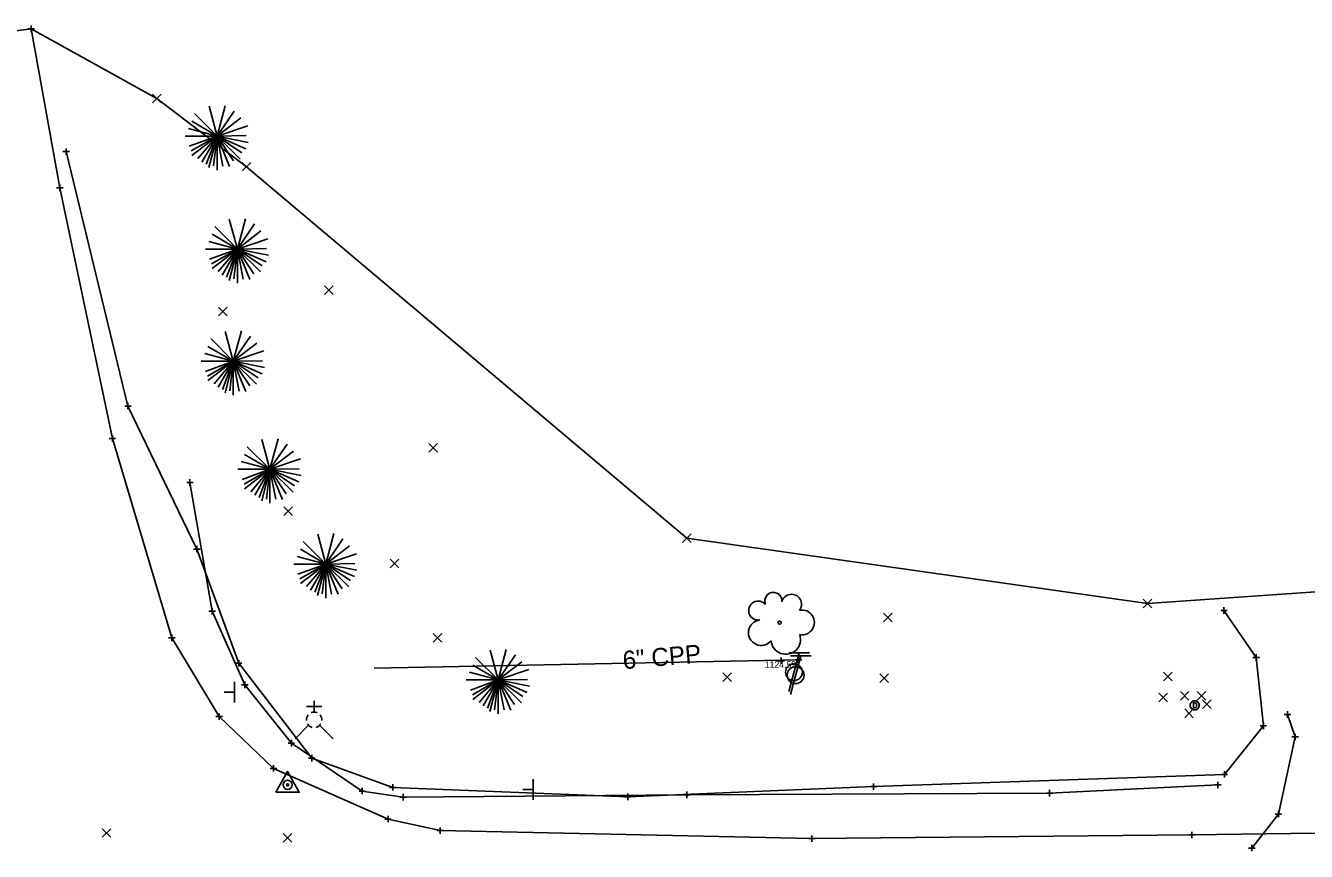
# Model space of a CAD drawing. Extents: x 146022 to 147632, y 437624 to 440659.
# Drawn here: x 147167.5 to 147365.2, y 438638.5 to 438766 of the extents above; entities that cross this region are included whole.
import ezdxf

# ---------------------------------------------------------------- set-up
doc = ezdxf.new("R2010")
doc.units = 0
for name, color, linetype in [('_CIVIL_CONSTRUCTION', 7, 'Continuous'), ('DR_P_Paved_Gutter', 7, 'Continuous'), ('DR_X_Storm_Sewer', 7, 'Continuous'), ('DR_X_Text', 7, 'Continuous'), ('DT_X_Break_Line', 7, 'Continuous'), ('DT_X_Triangles', 7, 'Continuous'), ('DT_X_Void', 7, 'Continuous'), ('PF_X_Ground_Line', 7, 'Continuous'), ('PV_P_Joint', 7, 'Continuous'), ('RD_P_Anchor_Assembly', 7, 'Continuous'), ('RD_P_GR_Lt_Replaced', 7, 'Continuous'), ('RD_P_GR_Rt', 7, 'Continuous'), ('SC_Scratch1', 7, 'Continuous'), ('SN_X_Post', 7, 'Continuous'), ('SV_X_Terrain_Boundary', 7, 'Continuous'), ('UT_X_Electric', 7, 'Continuous'), ('UT_X_Overhead_Cable_TV', 7, 'Continuous'), ('UT_X_Overhead_Electric', 7, 'Continuous')]:
    doc.layers.add(name, color=color, linetype=linetype)

msp = doc.modelspace()

# ---------------------------------------------------------------- linework, layer by layer
at = {"layer": '_CIVIL_CONSTRUCTION'}
for p, q in [((147187.08, 438754.06), (147188.42, 438755.39)), ((147187.08, 438755.39), (147188.42, 438754.06)), ((147200.92, 438743.53), (147202.25, 438744.86)), ((147200.92, 438744.86), (147202.25, 438743.53)), ((147213.61, 438724.44), (147214.94, 438725.78)), ((147213.61, 438725.78), (147214.94, 438724.44)), ((147197.27, 438721.15), (147198.61, 438722.49)), ((147197.27, 438722.49), (147198.61, 438721.15)), ((147229.75, 438700.13), (147231.09, 438701.47)), ((147229.75, 438701.47), (147231.09, 438700.13)), ((147207.34, 438690.37), (147208.68, 438691.7)), ((147207.34, 438691.7), (147208.68, 438690.37)), ((147268.91, 438686.18), (147270.24, 438687.51)), ((147268.91, 438687.51), (147270.24, 438686.18)), ((147223.75, 438682.28), (147225.09, 438683.61)), ((147223.75, 438683.61), (147225.09, 438682.28)), ((147340.04, 438676.1), (147341.37, 438677.43)), ((147340.04, 438677.43), (147341.37, 438676.1)), ((147299.92, 438673.96), (147301.25, 438675.29)), ((147299.92, 438675.29), (147301.25, 438673.96)), ((147230.4, 438670.78), (147231.73, 438672.11)), ((147230.4, 438672.11), (147231.73, 438670.78)), ((147275.12, 438664.72), (147276.45, 438666.05)), ((147275.12, 438666.05), (147276.45, 438664.72)), ((147299.39, 438664.59), (147300.72, 438665.93)), ((147299.39, 438665.93), (147300.72, 438664.59)), ((147343.19, 438664.81), (147344.53, 438666.14)), ((147343.19, 438666.14), (147344.53, 438664.81)), ((147345.77, 438661.83), (147347.1, 438663.16)), ((147345.77, 438663.16), (147347.1, 438661.83)), ((147348.39, 438661.86), (147349.72, 438663.2)), ((147348.39, 438663.2), (147349.72, 438661.86)), ((147342.47, 438661.6), (147343.8, 438662.94)), ((147342.47, 438662.94), (147343.8, 438661.6)), ((147349.2, 438660.55), (147350.53, 438661.88)), ((147349.2, 438661.88), (147350.53, 438660.55)), ((147346.44, 438659.14), (147347.77, 438660.48)), ((147346.44, 438660.48), (147347.77, 438659.14)), ((147179.31, 438640.67), (147180.64, 438642)), ((147179.31, 438642), (147180.64, 438640.67)), ((147207.23, 438639.94), (147208.56, 438641.27)), ((147207.23, 438641.27), (147208.56, 438639.94))]:
    msp.add_line(p, q, dxfattribs=at)
at = {"layer": 'DR_P_Paved_Gutter'}
msp.add_lwpolyline([(147351.58, 438648.75), (147325.59, 438647.48), (147269.59, 438647.22), (147225.76, 438646.86), (147219.46, 438647.81), (147208.51, 438655.2), (147201.32, 438664.21), (147196.28, 438675.56), (147192.84, 438695.44)], dxfattribs=at)
at = {"layer": 'DR_X_Storm_Sewer'}
msp.add_line((147286.81, 438668.08), (147221.27, 438666.79), dxfattribs=at)
at = {"layer": 'DT_X_Break_Line'}
for p, q in [((147199.73, 438664.67), (147199.73, 438661.47)), ((147199.73, 438663.07), (147198.13, 438663.07))]:
    msp.add_line(p, q, dxfattribs=at)
at = {"layer": 'DT_X_Triangles'}
msp.add_line((147347.98, 438661.05), (147347.98, 438661.05), dxfattribs=at)
msp.add_line((147347.98, 438661.05), (147347.98, 438661.05), dxfattribs=at)
msp.add_line((147347.98, 438661.05), (147347.98, 438661.05), dxfattribs=at)
msp.add_line((147347.98, 438661.05), (147347.98, 438661.05), dxfattribs=at)
msp.add_line((147347.98, 438661.05), (147347.98, 438661.05), dxfattribs=at)
msp.add_circle((147347.98, 438661.05), 0.7, dxfattribs=at)
at = {"layer": 'DT_X_Void'}
for p, q in [((147197.02, 438748.91), (147193.53, 438752.39)), ((147197.02, 438748.91), (147195.79, 438753.52)), ((147197.02, 438748.91), (147198.28, 438753.6)), ((147197.02, 438748.91), (147199.68, 438752.79)), ((147197.02, 438748.91), (147193.11, 438751.2)), ((147197.02, 438748.91), (147200.68, 438751.71)), ((147197.02, 438748.91), (147201.76, 438750.51)), ((147192.09, 438748.91), (147197.02, 438748.91)), ((147197.02, 438748.91), (147192.61, 438750.09)), ((147197.02, 438748.91), (147192.73, 438747.34)), ((147197.02, 438748.91), (147193.04, 438746.62)), ((147197.02, 438748.91), (147193.11, 438745.91)), ((147197.02, 438748.91), (147194.08, 438745.44)), ((147197.02, 438748.91), (147194.7, 438744.89)), ((147197.02, 438748.91), (147195.36, 438744.57)), ((147197.02, 438748.91), (147195.76, 438744.05)), ((147197.02, 438748.91), (147196.48, 438744.31)), ((147197.02, 438748.91), (147201.53, 438749)), ((147197.02, 438743.67), (147197.02, 438748.91)), ((147197.02, 438748.91), (147197.94, 438744.27)), ((147197.02, 438748.91), (147198.95, 438744.24)), ((147197.02, 438748.91), (147199.56, 438745.11)), ((147197.02, 438748.91), (147200.61, 438745.38)), ((147197.02, 438748.91), (147200.84, 438746.35)), ((147197.02, 438748.91), (147201.49, 438746.96)), ((147197.02, 438748.91), (147201.85, 438747.95)), ((147200.16, 438731.47), (147196.67, 438734.95)), ((147200.16, 438731.47), (147198.92, 438736.08)), ((147200.16, 438731.47), (147201.41, 438736.17)), ((147200.16, 438731.47), (147202.81, 438735.35)), ((147200.16, 438731.47), (147195.74, 438732.65)), ((147200.16, 438731.47), (147196.25, 438733.76)), ((147200.16, 438731.47), (147203.81, 438734.27)), ((147200.16, 438731.47), (147204.89, 438733.07)), ((147195.22, 438731.47), (147200.16, 438731.47)), ((147200.16, 438731.47), (147195.87, 438729.91)), ((147200.16, 438731.47), (147196.17, 438729.19)), ((147200.16, 438731.47), (147196.25, 438728.47)), ((147200.16, 438731.47), (147197.21, 438728)), ((147200.16, 438731.47), (147197.84, 438727.45)), ((147200.16, 438731.47), (147198.49, 438727.13)), ((147200.16, 438731.47), (147198.89, 438726.61)), ((147200.16, 438731.47), (147199.61, 438726.88)), ((147200.16, 438731.47), (147204.67, 438731.56)), ((147200.16, 438726.23), (147200.16, 438731.47)), ((147200.16, 438731.47), (147201.08, 438726.83)), ((147200.16, 438731.47), (147202.09, 438726.8)), ((147200.16, 438731.47), (147202.69, 438727.67)), ((147200.16, 438731.47), (147203.74, 438727.95)), ((147200.16, 438731.47), (147203.98, 438728.91)), ((147200.16, 438731.47), (147204.62, 438729.53)), ((147200.16, 438731.47), (147204.98, 438730.51)), ((147199.54, 438714.16), (147198.3, 438718.77)), ((147199.54, 438714.16), (147200.79, 438718.86)), ((147199.54, 438714.16), (147196.05, 438717.65)), ((147199.54, 438714.16), (147202.19, 438718.05)), ((147199.54, 438714.16), (147203.19, 438716.97)), ((147199.54, 438714.16), (147195.12, 438715.34)), ((147199.54, 438714.16), (147195.63, 438716.46)), ((147199.54, 438714.16), (147204.27, 438715.77)), ((147194.6, 438714.16), (147199.54, 438714.16)), ((147199.54, 438714.16), (147195.25, 438712.6)), ((147199.54, 438714.16), (147195.55, 438711.88)), ((147199.54, 438714.16), (147195.63, 438711.17)), ((147199.54, 438714.16), (147196.59, 438710.69)), ((147199.54, 438714.16), (147197.22, 438710.15)), ((147199.54, 438714.16), (147197.87, 438709.82)), ((147199.54, 438714.16), (147198.27, 438709.3)), ((147199.54, 438714.16), (147199, 438709.57)), ((147199.54, 438714.16), (147204.05, 438714.25)), ((147199.54, 438708.92), (147199.54, 438714.16)), ((147199.54, 438714.16), (147200.46, 438709.52)), ((147199.54, 438714.16), (147201.47, 438709.49)), ((147199.54, 438714.16), (147202.07, 438710.37)), ((147199.54, 438714.16), (147203.13, 438710.64)), ((147199.54, 438714.16), (147203.36, 438711.61)), ((147199.54, 438714.16), (147204, 438712.22)), ((147199.54, 438714.16), (147204.37, 438713.2)), ((147205.18, 438697.48), (147201.69, 438700.97)), ((147205.18, 438697.48), (147203.95, 438702.1)), ((147205.18, 438697.48), (147206.44, 438702.18)), ((147205.18, 438697.48), (147207.84, 438701.37)), ((147205.18, 438697.48), (147201.28, 438699.78)), ((147205.18, 438697.48), (147208.84, 438700.29)), ((147205.18, 438697.48), (147209.92, 438699.09)), ((147200.25, 438697.48), (147205.18, 438697.48)), ((147205.18, 438697.48), (147200.77, 438698.67)), ((147205.18, 438697.48), (147200.89, 438695.92)), ((147205.18, 438697.48), (147201.2, 438695.2)), ((147205.18, 438697.48), (147201.28, 438694.49)), ((147205.18, 438697.48), (147202.24, 438694.02)), ((147205.18, 438697.48), (147202.87, 438693.47)), ((147205.18, 438697.48), (147203.52, 438693.14)), ((147205.18, 438697.48), (147203.92, 438692.63)), ((147205.18, 438697.48), (147204.64, 438692.89)), ((147205.18, 438697.48), (147209.69, 438697.57)), ((147205.18, 438692.24), (147205.18, 438697.48)), ((147205.18, 438697.48), (147206.11, 438692.85)), ((147205.18, 438697.48), (147207.12, 438692.81)), ((147205.18, 438697.48), (147207.72, 438693.69)), ((147205.18, 438697.48), (147208.77, 438693.96)), ((147205.18, 438697.48), (147209.01, 438694.93)), ((147205.18, 438697.48), (147209.65, 438695.54)), ((147205.18, 438697.48), (147210.01, 438696.52)), ((147213.8, 438682.85), (147212.57, 438687.46)), ((147213.8, 438682.85), (147215.06, 438687.55)), ((147213.8, 438682.85), (147209.89, 438685.14)), ((147213.8, 438682.85), (147210.31, 438686.33)), ((147213.8, 438682.85), (147216.46, 438686.73)), ((147213.8, 438682.85), (147217.46, 438685.65)), ((147213.8, 438682.85), (147209.39, 438684.03)), ((147213.8, 438682.85), (147218.54, 438684.45)), ((147213.8, 438682.85), (147218.31, 438682.94)), ((147208.87, 438682.85), (147213.8, 438682.85)), ((147213.8, 438682.85), (147209.51, 438681.29)), ((147213.8, 438682.85), (147209.82, 438680.57)), ((147213.8, 438682.85), (147209.89, 438679.85)), ((147213.8, 438682.85), (147210.86, 438679.38)), ((147213.8, 438682.85), (147211.48, 438678.83)), ((147213.8, 438682.85), (147212.14, 438678.51)), ((147213.8, 438682.85), (147212.54, 438677.99)), ((147213.8, 438682.85), (147213.26, 438678.26)), ((147213.8, 438677.61), (147213.8, 438682.85)), ((147213.8, 438682.85), (147214.72, 438678.21)), ((147213.8, 438682.85), (147215.73, 438678.18)), ((147213.8, 438682.85), (147216.34, 438679.05)), ((147213.8, 438682.85), (147217.39, 438679.33)), ((147213.8, 438682.85), (147217.62, 438680.29)), ((147213.8, 438682.85), (147218.27, 438680.91)), ((147213.8, 438682.85), (147218.63, 438681.89)), ((147240.43, 438664.96), (147239.2, 438669.58)), ((147240.43, 438664.96), (147241.69, 438669.66)), ((147240.43, 438664.96), (147236.53, 438667.26)), ((147240.43, 438664.96), (147236.94, 438668.45)), ((147240.43, 438664.96), (147243.09, 438668.85)), ((147240.43, 438664.96), (147244.09, 438667.77)), ((147240.43, 438664.96), (147236.02, 438666.15)), ((147240.43, 438664.96), (147245.17, 438666.57)), ((147235.5, 438664.96), (147240.43, 438664.96)), ((147240.43, 438664.96), (147236.14, 438663.4)), ((147240.43, 438664.96), (147236.45, 438662.68)), ((147240.43, 438664.96), (147236.53, 438661.97)), ((147240.43, 438664.96), (147237.49, 438661.5)), ((147240.43, 438664.96), (147238.12, 438660.95)), ((147240.43, 438664.96), (147238.77, 438660.62)), ((147240.43, 438664.96), (147239.17, 438660.11)), ((147240.43, 438664.96), (147239.89, 438660.37)), ((147240.43, 438664.96), (147244.94, 438665.05)), ((147240.43, 438659.72), (147240.43, 438664.96)), ((147240.43, 438664.96), (147241.36, 438660.33)), ((147240.43, 438664.96), (147242.37, 438660.29)), ((147240.43, 438664.96), (147242.97, 438661.17)), ((147240.43, 438664.96), (147244.02, 438661.44)), ((147240.43, 438664.96), (147244.26, 438662.41)), ((147240.43, 438664.96), (147244.9, 438663.02)), ((147240.43, 438664.96), (147245.26, 438664))]:
    msp.add_line(p, q, dxfattribs=at)
msp.add_circle((147283.9, 438673.81), 0.24, dxfattribs=at)
for centre, radius, start, end in [((147280.59, 438675.67), 1.47, 39.0625, 279.5412), ((147282.92, 438677.17), 1.32, 354.0047, 205.9741), ((147285.73, 438676.64), 1.55, 323.83, 165.0376), ((147287.36, 438673.84), 1.91, 259.1453, 101.4596), ((147281.05, 438672.26), 1.97, 96.1722, 320.5737), ((147284.85, 438671.2), 2.28, 184.9476, 19.4572)]:
    msp.add_arc(centre, radius, start, end, dxfattribs=at)
at = {"layer": 'PF_X_Ground_Line'}
msp.add_lwpolyline([(147173.73, 438746.52), (147183.27, 438707.24), (147193.9, 438685.17), (147200.38, 438667.53), (147211.65, 438652.9), (147224.18, 438648.38), (147260.44, 438646.93), (147298.41, 438648.5), (147352.57, 438650.38), (147358.6, 438657.89), (147357.48, 438668.43), (147352.5, 438675.68)], dxfattribs=at)
at = {"layer": 'PV_P_Joint'}
msp.add_lwpolyline([(147206.13, 438647.62), (147209.73, 438647.62), (147207.93, 438650.84)], close=True, dxfattribs=at)
for radius in [0.7, 0.16]:
    msp.add_circle((147207.93, 438648.77), radius, dxfattribs=at)
at = {"layer": 'RD_P_Anchor_Assembly'}
for p, q in [((147168.32, 438765.97), (147168.32, 438764.97)), ((147167.82, 438765.47), (147168.82, 438765.47)), ((147168.32, 438765.47), (147168.32, 438765.47)), ((147173.23, 438746.52), (147174.23, 438746.52)), ((147173.73, 438747.02), (147173.73, 438746.02)), ((147173.73, 438746.52), (147173.73, 438746.52)), ((147172.25, 438740.93), (147173.25, 438740.93)), ((147172.75, 438741.43), (147172.75, 438740.43)), ((147172.75, 438740.93), (147172.75, 438740.93)), ((147182.77, 438707.24), (147183.77, 438707.24)), ((147183.27, 438707.74), (147183.27, 438706.74)), ((147183.27, 438707.24), (147183.27, 438707.24)), ((147180.87, 438702.72), (147180.87, 438701.72)), ((147180.37, 438702.22), (147181.37, 438702.22)), ((147180.87, 438702.22), (147180.87, 438702.22)), ((147192.34, 438695.44), (147193.34, 438695.44)), ((147192.84, 438695.94), (147192.84, 438694.94)), ((147192.84, 438695.44), (147192.84, 438695.44)), ((147193.4, 438685.17), (147194.4, 438685.17)), ((147193.9, 438685.67), (147193.9, 438684.67)), ((147193.9, 438685.17), (147193.9, 438685.17)), ((147195.78, 438675.56), (147196.78, 438675.56)), ((147196.28, 438676.06), (147196.28, 438675.06)), ((147196.28, 438675.56), (147196.28, 438675.56)), ((147352, 438675.68), (147353, 438675.68)), ((147352.5, 438676.18), (147352.5, 438675.18)), ((147352.5, 438675.68), (147352.5, 438675.68)), ((147189.54, 438671.47), (147190.54, 438671.47)), ((147190.04, 438671.97), (147190.04, 438670.97)), ((147190.04, 438671.47), (147190.04, 438671.47)), ((147199.88, 438667.53), (147200.88, 438667.53)), ((147200.38, 438668.03), (147200.38, 438667.03)), ((147200.38, 438667.53), (147200.38, 438667.53)), ((147356.98, 438668.43), (147357.98, 438668.43)), ((147357.48, 438668.93), (147357.48, 438667.93)), ((147357.48, 438668.43), (147357.48, 438668.43)), ((147200.82, 438664.21), (147201.82, 438664.21)), ((147201.32, 438664.71), (147201.32, 438663.71)), ((147201.32, 438664.21), (147201.32, 438664.21)), ((147196.86, 438659.31), (147197.86, 438659.31)), ((147197.36, 438659.81), (147197.36, 438658.81)), ((147197.36, 438659.31), (147197.36, 438659.31)), ((147361.82, 438659.63), (147362.82, 438659.63)), ((147362.32, 438660.13), (147362.32, 438659.13)), ((147362.32, 438659.63), (147362.32, 438659.63)), ((147358.1, 438657.89), (147359.1, 438657.89)), ((147358.6, 438658.39), (147358.6, 438657.39)), ((147358.6, 438657.89), (147358.6, 438657.89)), ((147208.51, 438655.7), (147208.51, 438654.7)), ((147363, 438656.16), (147364, 438656.16)), ((147363.5, 438656.66), (147363.5, 438655.66)), ((147363.5, 438656.16), (147363.5, 438656.16)), ((147208.01, 438655.2), (147209.01, 438655.2)), ((147208.51, 438655.2), (147208.51, 438655.2)), ((147211.65, 438653.4), (147211.65, 438652.4)), ((147205.25, 438651.31), (147206.25, 438651.31)), ((147205.75, 438651.81), (147205.75, 438650.81)), ((147205.75, 438651.31), (147205.75, 438651.31)), ((147211.15, 438652.9), (147212.15, 438652.9)), ((147211.65, 438652.9), (147211.65, 438652.9)), ((147352.07, 438650.38), (147353.07, 438650.38)), ((147352.57, 438650.88), (147352.57, 438649.88)), ((147352.57, 438650.38), (147352.57, 438650.38)), ((147218.96, 438647.81), (147219.96, 438647.81)), ((147219.46, 438648.31), (147219.46, 438647.31)), ((147219.46, 438647.81), (147219.46, 438647.81)), ((147223.68, 438648.38), (147224.68, 438648.38)), ((147224.18, 438648.88), (147224.18, 438647.88)), ((147224.18, 438648.38), (147224.18, 438648.38)), ((147225.76, 438647.36), (147225.76, 438646.36)), ((147260.44, 438647.43), (147260.44, 438646.43)), ((147269.59, 438647.72), (147269.59, 438646.72)), ((147297.91, 438648.5), (147298.91, 438648.5)), ((147298.41, 438649), (147298.41, 438648)), ((147298.41, 438648.5), (147298.41, 438648.5)), ((147325.09, 438647.48), (147326.09, 438647.48)), ((147325.59, 438647.98), (147325.59, 438646.98)), ((147325.59, 438647.48), (147325.59, 438647.48)), ((147351.08, 438648.75), (147352.08, 438648.75)), ((147351.58, 438649.25), (147351.58, 438648.25)), ((147351.58, 438648.75), (147351.58, 438648.75)), ((147225.26, 438646.86), (147226.26, 438646.86)), ((147225.76, 438646.86), (147225.76, 438646.86)), ((147259.94, 438646.93), (147260.94, 438646.93)), ((147260.44, 438646.93), (147260.44, 438646.93)), ((147269.09, 438647.22), (147270.09, 438647.22)), ((147269.59, 438647.22), (147269.59, 438647.22)), ((147222.93, 438643.49), (147223.93, 438643.49)), ((147223.43, 438643.99), (147223.43, 438642.99)), ((147223.43, 438643.49), (147223.43, 438643.49)), ((147360.41, 438644.27), (147361.41, 438644.27)), ((147360.91, 438644.77), (147360.91, 438643.77)), ((147360.91, 438644.27), (147360.91, 438644.27)), ((147231, 438641.71), (147232, 438641.71)), ((147231.5, 438642.21), (147231.5, 438641.21)), ((147231.5, 438641.71), (147231.5, 438641.71)), ((147347.57, 438641.54), (147347.57, 438640.54)), ((147288.38, 438640.47), (147289.38, 438640.47)), ((147288.88, 438640.97), (147288.88, 438639.97)), ((147288.88, 438640.47), (147288.88, 438640.47)), ((147347.07, 438641.04), (147348.07, 438641.04)), ((147347.57, 438641.04), (147347.57, 438641.04)), ((147356.82, 438639.51), (147356.82, 438638.51)), ((147356.32, 438639.01), (147357.32, 438639.01)), ((147356.82, 438639.01), (147356.82, 438639.01))]:
    msp.add_line(p, q, dxfattribs=at)
at = {"layer": 'RD_P_GR_Lt_Replaced'}
msp.add_lwpolyline([(147168.32, 438765.47), (147172.75, 438740.93), (147180.87, 438702.22), (147190.04, 438671.47), (147197.36, 438659.31), (147205.75, 438651.31), (147223.43, 438643.49), (147231.5, 438641.71), (147288.88, 438640.47), (147347.57, 438641.04), (147397.16, 438641.73), (147409.97, 438641.17), (147442.47, 438641.05)], dxfattribs=at)
at = {"layer": 'RD_P_GR_Rt'}
for p, q in [((147212.02, 438660.01), (147212.02, 438661.73)), ((147213.22, 438660.87), (147210.82, 438660.87)), ((147211.17, 438657.96), (147209.09, 438655.88)), ((147212.02, 438658.81), (147212.02, 438658.81)), ((147212.02, 438658.81), (147212.02, 438658.81)), ((147212.87, 438657.96), (147214.95, 438655.88))]:
    msp.add_line(p, q, dxfattribs=at)
for start, end in [(140.021, 184.0629), (68.1395, 112.038), (356.0165, 39.9889), (211.8788, 255.8479), (283.8239, 329.9097)]:
    msp.add_arc((147212.02, 438658.81), 1.2, start, end, dxfattribs=at)
at = {"layer": 'SC_Scratch1'}
msp.add_lwpolyline([(147356.82, 438639.01), (147360.91, 438644.27), (147363.5, 438656.16), (147362.32, 438659.63)], dxfattribs=at)
at = {"layer": 'SN_X_Post'}
for p, q in [((147245.82, 438649.67), (147245.82, 438646.47)), ((147245.82, 438648.07), (147244.22, 438648.07)), ((147245.82, 438648.07), (147245.82, 438648.07))]:
    msp.add_line(p, q, dxfattribs=at)
at = {"layer": 'SV_X_Terrain_Boundary'}
msp.add_lwpolyline([(147113.81, 438520.22), (147177.01, 438554.45), (147231.16, 438565.21), (147265.76, 438561.91), (147390.47, 438583.18), (147427.48, 438581.67), (147447.86, 438583.13), (147451.41, 438585.81), (147462.29, 438588.25), (147470.97, 438613.92), (147441.54, 438616), (147443.52, 438625.99), (147442.63, 438637.34), (147442.47, 438641.05), (147440.21, 438644.72), (147444.24, 438659.07), (147444.23, 438674.06), (147411.94, 438681.71), (147340.71, 438676.77), (147269.57, 438686.84), (147201.59, 438744.19), (147187.75, 438754.72), (147168.32, 438765.47), (147156.85, 438763.96)], dxfattribs=at)
at = {"layer": 'UT_X_Electric'}
msp.add_lwpolyline([(147348.08, 438661.45), (147347.8, 438661.45), (147347.8, 438660.65), (147348.08, 438660.65)], dxfattribs=at)
for centre, radius, start, end in [((147347.98, 438661.05), 0.7, 150.0184, 209.9816), ((147347.98, 438661.05), 0.7, 60.0184, 120.0157), ((147347.83, 438661.05), 0.474, 302.5148, 57.4852), ((147347.98, 438661.05), 0.7, 330.0184, 29.9816), ((147347.98, 438661.05), 0.7, 239.9843, 299.9816)]:
    msp.add_arc(centre, radius, start, end, dxfattribs=at)
at = {"layer": 'UT_X_Overhead_Cable_TV'}
for p, q in [((147286.92, 438669.17), (147285.31, 438663.17)), ((147288.52, 438669.17), (147285.32, 438669.17)), ((147288.76, 438668.7), (147285.56, 438668.7)), ((147287.16, 438668.7), (147285.56, 438662.7))]:
    msp.add_line(p, q, dxfattribs=at)
for centre in [(147286.11, 438666.17), (147286.36, 438665.7)]:
    msp.add_circle(centre, 1.3, dxfattribs=at)
at = {"layer": 'UT_X_Overhead_Electric'}
for p, q in [((147283.64, 438667.94), (147284.64, 438667.94)), ((147284.14, 438668.44), (147284.14, 438667.44)), ((147284.14, 438667.94), (147284.14, 438667.94)), ((147286.31, 438668.08), (147287.31, 438668.08)), ((147286.81, 438668.58), (147286.81, 438667.58)), ((147286.81, 438668.08), (147286.81, 438668.08))]:
    msp.add_line(p, q, dxfattribs=at)

# ---------------------------------------------------------------- texts
at = {"layer": 'DR_X_Text'}
msp.add_text('6" CPP', height=2.8, rotation=5, dxfattribs=at).set_placement((147259.78, 438666.61))
at = {"layer": 'SC_Scratch1'}
msp.add_text("1124.59'", height=1, dxfattribs=at).set_placement((147281.6, 438666.86))

doc.saveas('drawing.dxf')
